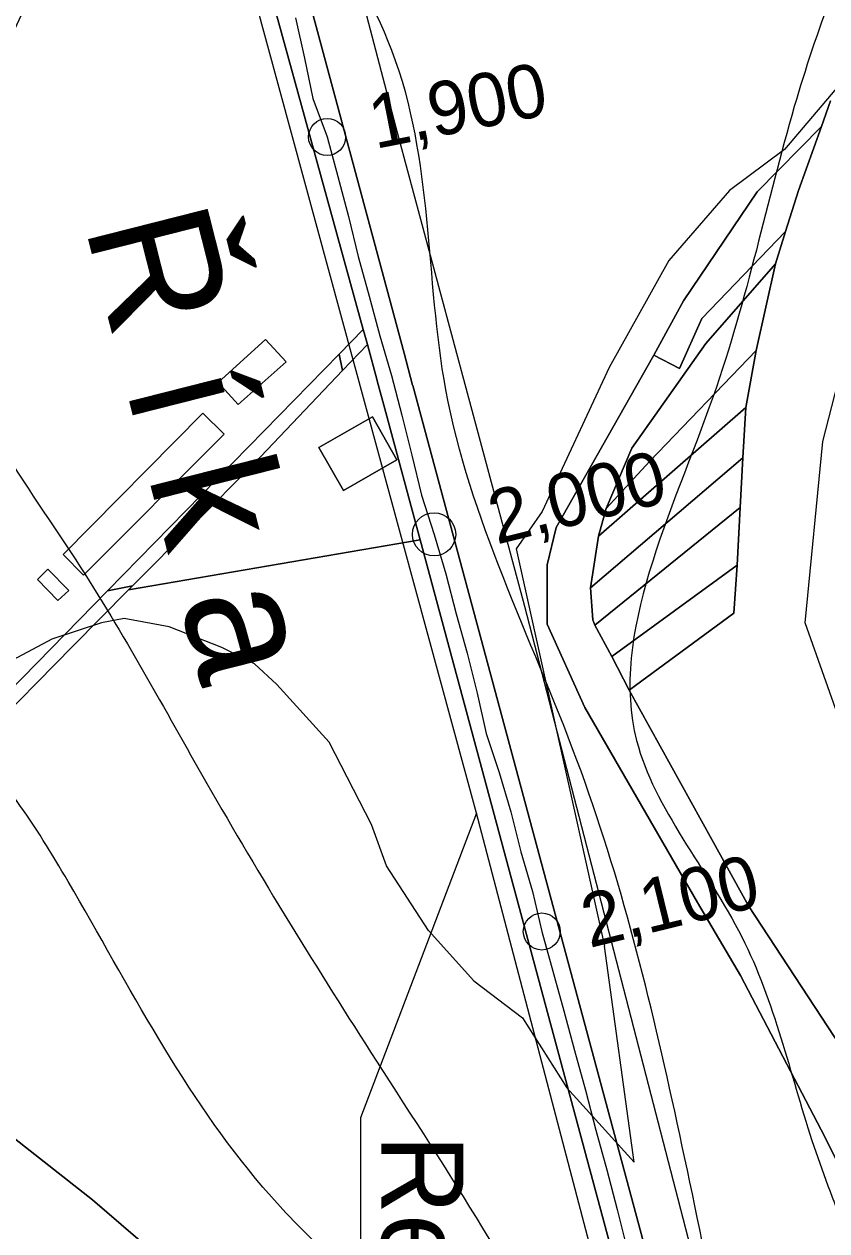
# Model space of a CAD drawing. Extents: x -510989 to -501240, y -1184665 to -1176089.
# Drawn here: x -504809.1 to -504614, y -1181469.7 to -1181176.6 of the extents above; entities that cross this region are included whole.
import ezdxf

# ---------------------------------------------------------------- set-up
doc = ezdxf.new("R2010")
doc.units = 0
for name, color, linetype in [('NAVRH_revitalizace_toku', 7, 'Continuous'), ('orna_puda', 7, 'Continuous'), ('ostatni_plocha_x_draha', 7, 'Continuous'), ('ostatni_plocha_x_jina_plocha', 7, 'Continuous'), ('ostatni_plocha_x_ostatni_komunikace', 7, 'Continuous'), ('ostatni_plocha_x_sportoviste_a_rekr_plocha', 7, 'Continuous'), ('STAV_zaplavove_uzemi', 7, 'Continuous'), ('trasovani_toku', 7, 'Continuous'), ('vodni_plocha_x_vodni_tok_v_koryt_prir_n_upr', 7, 'Continuous'), ('vrstevnice_01', 7, 'Continuous'), ('vrstevnice_02', 7, 'Continuous'), ('zastavena_plocha_a_nadvori', 7, 'Continuous')]:
    doc.layers.add(name, color=color, linetype=linetype)

msp = doc.modelspace()

# ---------------------------------------------------------------- linework, layer by layer
at = {"layer": 'NAVRH_revitalizace_toku'}
for points in [[(-504182.04, -1180792.04), (-504204.87, -1180813.12), (-504441.3, -1180893.49), (-504535.64, -1180920.73), (-504547.6, -1180927.38), (-504622.01, -1180977.87), (-504664.53, -1181014.41), (-504691.11, -1181051.62), (-504730.92, -1181097.66), (-504738.16, -1181127.41), (-504718.87, -1181201.36), (-504687.51, -1181317.93), (-504646.6, -1181475.99), (-504595.04, -1181660.81)], [(-504619.38, -1181665.94), (-504652.45, -1181546.29), (-504699.14, -1181368.28), (-504767.85, -1181115.82)], [(-504699.14, -1181368.28), (-504727.32, -1181442.23), (-504727.15, -1181617.42)]]:
    msp.add_lwpolyline(points, dxfattribs=at)
at = {"layer": 'orna_puda'}
for points in [[(-504609.62, -1181654.37), (-504714.66, -1181264.33), (-504714.68, -1181264.25), (-504716.76, -1181256.52), (-504751.58, -1181127.22), (-504752.67, -1181115.82), (-504749.63, -1181100.59), (-504733.91, -1181066.63), (-504677.14, -1181000.88), (-504645.58, -1180971.03), (-504557.05, -1180910.28)], [(-504613.13, -1181195.22), (-504615.31, -1181201.45), (-504630.96, -1181217.3), (-504648.9, -1181243.78), (-504656.11, -1181257), (-504679.79, -1181298.82), (-504681.95, -1181307.89), (-504681.99, -1181322.34), (-504672.85, -1181342.61), (-504645.47, -1181389.98), (-504634.98, -1181407.71), (-504614.42, -1181447.03), (-504604.62, -1181466.71)], [(-504604.62, -1181466.71), (-504614.42, -1181447.03), (-504634.98, -1181407.71), (-504645.47, -1181389.98), (-504672.85, -1181342.61), (-504681.99, -1181322.34), (-504681.95, -1181307.89), (-504679.79, -1181298.82), (-504656.11, -1181257), (-504649.83, -1181260.24), (-504644.42, -1181248.07), (-504624.08, -1181226.97), (-504626.48, -1181234.83), (-504643.41, -1181254.13), (-504661.43, -1181279.57), (-504667.62, -1181294.22), (-504669.52, -1181300.97), (-504671.47, -1181313.52), (-504670.91, -1181321.27), (-504670.38, -1181322.61), (-504666.3, -1181330.17), (-504662.07, -1181338.33), (-504641.94, -1181374.66), (-504633.05, -1181390.72), (-504607.29, -1181430.02)], [(-504833.48, -1181474.49), (-504875.32, -1181461.1), (-504900.47, -1181432.41), (-504866.87, -1181398.49), (-504862.77, -1181403.54), (-504857.98, -1181408.64), (-504847.86, -1181418.69), (-504792.48, -1181462.19), (-504731.58, -1181514.6)]]:
    msp.add_lwpolyline(points, dxfattribs=at)
for points in [[(-504615.31, -1181201.45), (-504620.93, -1181217), (-504624.08, -1181226.97), (-504644.42, -1181248.07), (-504649.83, -1181260.24), (-504656.11, -1181257), (-504648.9, -1181243.78), (-504630.96, -1181217.3)], [(-504626.48, -1181234.83), (-504631.24, -1181255.86), (-504657.03, -1181282.77), (-504667.62, -1181294.22), (-504661.43, -1181279.57), (-504643.41, -1181254.13)], [(-504725.66, -1181254.39), (-504723.31, -1181263.13), (-504723.29, -1181263.22), (-504721.2, -1181270.94), (-504712.86, -1181301.83), (-504783.7, -1181313.99), (-504782.76, -1181313.04), (-504753.12, -1181283.2), (-504731.68, -1181260.7)], [(-504631.24, -1181255.86), (-504633.68, -1181269.68), (-504669.52, -1181300.97), (-504667.62, -1181294.22), (-504657.03, -1181282.77)], [(-504737.48, -1181279.46), (-504731.51, -1181289.87), (-504718.49, -1181282.4), (-504724.47, -1181271.99)], [(-504633.68, -1181269.68), (-504634.41, -1181281.92), (-504671.47, -1181313.52), (-504669.52, -1181300.97)], [(-504634.41, -1181281.92), (-504635.12, -1181294), (-504670.38, -1181322.61), (-504670.91, -1181321.27), (-504671.47, -1181313.52)], [(-504635.12, -1181294), (-504635.8, -1181308), (-504666.3, -1181330.17), (-504670.38, -1181322.61)], [(-504783.7, -1181313.99), (-504712.86, -1181301.83), (-504662.52, -1181488.46), (-504731.58, -1181514.6), (-504792.48, -1181462.19), (-504847.86, -1181418.69), (-504857.98, -1181408.64), (-504862.77, -1181403.54), (-504866.87, -1181398.49), (-504866.31, -1181397.92), (-504864.53, -1181396.11), (-504862.24, -1181393.77), (-504797.28, -1181327.66)], [(-504635.8, -1181308), (-504636.64, -1181319.66), (-504662.07, -1181338.33), (-504666.3, -1181330.17)]]:
    msp.add_lwpolyline(points, close=True, dxfattribs=at)
at = {"layer": 'ostatni_plocha_x_draha'}
msp.add_lwpolyline([(-504607.29, -1181430.02), (-504633.05, -1181390.72), (-504641.94, -1181374.66), (-504662.07, -1181338.33), (-504636.64, -1181319.66), (-504635.8, -1181308), (-504635.12, -1181294), (-504634.41, -1181281.92), (-504633.68, -1181269.68), (-504631.24, -1181255.86), (-504626.48, -1181234.83), (-504624.08, -1181226.97), (-504620.93, -1181217), (-504615.31, -1181201.45), (-504613.13, -1181195.22)], dxfattribs=at)
at = {"layer": 'ostatni_plocha_x_jina_plocha'}
msp.add_lwpolyline([(-504737.48, -1181279.46), (-504724.47, -1181271.99), (-504718.49, -1181282.4), (-504731.51, -1181289.87)], close=True, dxfattribs=at)
at = {"layer": 'ostatni_plocha_x_ostatni_komunikace'}
for points in [[(-504726.28, -1181252.1), (-504725.66, -1181254.39), (-504731.68, -1181260.7), (-504732.57, -1181256.77), (-504726.66, -1181250.72)], [(-504731.68, -1181260.7), (-504753.12, -1181283.2), (-504782.76, -1181313.04), (-504788.79, -1181314.23), (-504750.73, -1181275.38), (-504732.57, -1181256.77)], [(-504783.7, -1181313.99), (-504797.28, -1181327.66), (-504862.24, -1181393.77), (-504864.28, -1181391.38), (-504788.79, -1181314.23), (-504782.76, -1181313.04)]]:
    msp.add_lwpolyline(points, close=True, dxfattribs=at)
at = {"layer": 'ostatni_plocha_x_sportoviste_a_rekr_plocha'}
msp.add_lwpolyline([(-504760.66, -1181127.46), (-504726.66, -1181250.72), (-504732.57, -1181256.77), (-504750.73, -1181275.38), (-504788.79, -1181314.23), (-504864.28, -1181391.38), (-504904.47, -1181432.44), (-504902.62, -1181434.58), (-504905.19, -1181437.02), (-504905.4, -1181440.61), (-504905.46, -1181441.72), (-504910.13, -1181446.83), (-504925.8, -1181463.98), (-504930.57, -1181459.1), (-505050.59, -1181336.35)], dxfattribs=at)
for points in [[(-504745.4, -1181258.63), (-504750.41, -1181253.22), (-504761.95, -1181263.61), (-504757.11, -1181269.01)], [(-504760.5, -1181276.22), (-504765.62, -1181271.1), (-504799.58, -1181305.39), (-504794.66, -1181310.46)], [(-504805.8, -1181311.48), (-504800.88, -1181316.62), (-504798.2, -1181314.14), (-504803.33, -1181308.99)]]:
    msp.add_lwpolyline(points, close=True, dxfattribs=at)
at = {"layer": 'STAV_zaplavove_uzemi'}
for points in [[(-504594.17, -1181642.09), (-504629.77, -1181535.28), (-504650.39, -1181443.46), (-504674.75, -1181355.39), (-504706.6, -1181265.44), (-504719.72, -1181182.99), (-504747.83, -1181113.66), (-504727.29, -1181064.42), (-504683.65, -1181020.77), (-504624.52, -1180967.28), (-504575.24, -1180927.85), (-504544.27, -1180915.18), (-504445.72, -1180881.39), (-504404.89, -1180867.31), (-504292.26, -1180829.3), (-504179.63, -1180791.29), (-504099.38, -1180734.98), (-504020.54, -1180698.37), (-503957.18, -1180675.84), (-503893.83, -1180664.58), (-503865.67, -1180678.66), (-503817.8, -1180689.92), (-503788.24, -1180689.92), (-503764.3, -1180695.55), (-503736.15, -1180687.11), (-503717.85, -1180698.37), (-503716.44, -1180708.23)], [(-502250.32, -1184002.61), (-502355.07, -1183875.41), (-502442.37, -1183790.61), (-502477.29, -1183700.82), (-502532.16, -1183578.61), (-502567.08, -1183448.91), (-502626.05, -1183402.34), (-502705.41, -1183380.59), (-502814.2, -1183349.87), (-502882.03, -1183297.39), (-502931.95, -1183237.24), (-503042.02, -1183107.97), (-503139.64, -1183018.94), (-503222.14, -1182957.59), (-503308.56, -1182839.96), (-503316.24, -1182784.92), (-503330.32, -1182756.77), (-503348.24, -1182719.65), (-503334.16, -1182651.82), (-503323.92, -1182595.5), (-503313.68, -1182526.39), (-503294.1, -1182480.5), (-503251.86, -1182396.03), (-503229.34, -1182314.37), (-503216.1, -1182227.15), (-503242.43, -1182174.5), (-503271.86, -1182129.59), (-503287.34, -1182081.58), (-503343.88, -1182028.1), (-503361.79, -1182008.91), (-503396.35, -1181952.59), (-503442.43, -1181933.39), (-503497.46, -1181888.6), (-503525.62, -1181860.44), (-503528.18, -1181837.4), (-503548.66, -1181767.01), (-503558.9, -1181729.89), (-503576.82, -1181682.53), (-503578.1, -1181621.1), (-503567.86, -1181572.46), (-503552.5, -1181536.63), (-503538.04, -1181458.36), (-503518.33, -1181411.9), (-503509.88, -1181341.51), (-503497.21, -1181207.63), (-503499.77, -1181097.56), (-503498.02, -1181031.35), (-503510.82, -1180970.85), (-503549.22, -1180952.23), (-503571.32, -1180940.6), (-503605.07, -1180937.11), (-503651.61, -1180939.44), (-503671.39, -1180917.33), (-503679.53, -1180892.89), (-503713.27, -1180871.95), (-503727.24, -1180859.15), (-503734.22, -1180833.55), (-503728.4, -1180799.81), (-503741.2, -1180770.72), (-503722.82, -1180725.17), (-503721.54, -1180703.41), (-503731.78, -1180697.01), (-503767.61, -1180699.57), (-503790.65, -1180697.01), (-503817.53, -1180697.01), (-503861.04, -1180686.77), (-503889.2, -1180675.25), (-503900.72, -1180668.85), (-503953.2, -1180679.09), (-503997.99, -1180697.01), (-504063.27, -1180722.61), (-504109.34, -1180749.49), (-504142.62, -1180776.36), (-504177.18, -1180796.84), (-504211.73, -1180817.32), (-504414.98, -1180961.5), (-504472.7, -1180998.11), (-504544.51, -1181068.5), (-504600.82, -1181143.12), (-504621.94, -1181196.62), (-504641.65, -1181267.01), (-504660.25, -1181350.62), (-504634.7, -1181398.32), (-504617.66, -1181447.72), (-504600.62, -1181492.01), (-504587, -1181548.23), (-504592.11, -1181628.29), (-504569.96, -1181682.81), (-504568.26, -1181664.07), (-504554.63, -1181621.48), (-504547.82, -1181597.63)], [(-504826.46, -1182247.73), (-504827.62, -1182204.68), (-504817.15, -1182165.12), (-504791.55, -1182113.93), (-504727.56, -1182034.81), (-504708.94, -1182017.35), (-504669.38, -1181991.76), (-504649.6, -1181961.5), (-504628.66, -1181917.29), (-504601.9, -1181867.26), (-504597.24, -1181809.08), (-504585.16, -1181766.79), (-504596.8, -1181741.4), (-504604.2, -1181726.59), (-504633.82, -1181658.9), (-504646.51, -1181600.72), (-504660.26, -1181556.29), (-504751.04, -1181459.08), (-504798.4, -1181384.84), (-504826.55, -1181347.73), (-504862.39, -1181315.73), (-504866.23, -1181265.81), (-504862.39, -1181205.66), (-504853.43, -1181164.7), (-504793.92, -1181116.47), (-504755.84, -1181064.64), (-504725.17, -1181018.1), (-504649.01, -1180947.23), (-504594, -1180900.69), (-504545.35, -1180879.53), (-504377.38, -1180832.83), (-504317.01, -1180808.36), (-504368.93, -1180802.59), (-504426.63, -1180826.63), (-504542.02, -1180859.32)], [(-504777.81, -1181111.78), (-504815.29, -1181186.74), (-504828.41, -1181242.96), (-504796.55, -1181306.67), (-504764.69, -1181361.01), (-504723.47, -1181428.47), (-504674.75, -1181510.92), (-504648.51, -1181582.13), (-504622.28, -1181672.07)]]:
    msp.add_spline(points, degree=3, dxfattribs=at)
at = {"layer": 'trasovani_toku'}
for p, q in [((-504743.16, -1181175.06), (-504740.99, -1181184.83)), ((-504740.99, -1181184.83), (-504738.96, -1181194.62)), ((-504738.96, -1181194.62), (-504735.46, -1181203.99)), ((-504735.46, -1181203.99), (-504732.82, -1181213.63)), ((-504732.82, -1181213.63), (-504730.24, -1181223.29)), ((-504730.24, -1181223.29), (-504727.94, -1181233.03)), ((-504727.94, -1181233.03), (-504725.21, -1181242.64)), ((-504725.21, -1181242.64), (-504722.64, -1181252.31)), ((-504722.64, -1181252.31), (-504719.82, -1181261.9)), ((-504719.82, -1181261.9), (-504717.32, -1181271.59)), ((-504717.32, -1181271.59), (-504714.88, -1181281.28)), ((-504714.88, -1181281.28), (-504712.54, -1181291)), ((-504712.54, -1181291), (-504709.47, -1181300.52)), ((-504709.47, -1181300.52), (-504706.61, -1181310.1)), ((-504706.61, -1181310.1), (-504704.11, -1181319.79)), ((-504704.11, -1181319.79), (-504701.42, -1181329.42)), ((-504701.42, -1181329.42), (-504698.97, -1181339.12)), ((-504698.97, -1181339.12), (-504696.79, -1181348.87)), ((-504696.79, -1181348.87), (-504693.66, -1181358.37)), ((-504693.66, -1181358.37), (-504690.81, -1181367.96)), ((-504690.81, -1181367.96), (-504688.41, -1181377.66)), ((-504688.41, -1181377.66), (-504685.53, -1181387.24)), ((-504685.53, -1181387.24), (-504683.29, -1181396.99)), ((-504683.29, -1181396.99), (-504680.61, -1181406.62)), ((-504680.61, -1181406.62), (-504677.97, -1181416.26)), ((-504677.97, -1181416.26), (-504675.38, -1181425.92)), ((-504675.38, -1181425.92), (-504672.71, -1181435.56)), ((-504672.71, -1181435.56), (-504670.16, -1181445.23)), ((-504670.16, -1181445.23), (-504667.51, -1181454.87)), ((-504667.51, -1181454.87), (-504664.94, -1181464.54)), ((-504664.94, -1181464.54), (-504662.53, -1181474.24))]:
    msp.add_line(p, q, dxfattribs=at)
for centre, radius in [((-504735.46, -1181203.99), 4.5), ((-504709.47, -1181300.52), 5.25), ((-504683.29, -1181396.99), 4.5)]:
    msp.add_circle(centre, radius, dxfattribs=at)
at = {"layer": 'vodni_plocha_x_vodni_tok_v_koryt_prir_n_upr'}
for points in [[(-504608.12, -1181659.96), (-504614.86, -1181665.13), (-504632.61, -1181599.34), (-504645.61, -1181551.13), (-504655.26, -1181515.38), (-504662.52, -1181488.46), (-504712.86, -1181301.83), (-504721.2, -1181270.94), (-504723.29, -1181263.22), (-504723.31, -1181263.13), (-504725.66, -1181254.39), (-504726.28, -1181252.1), (-504726.66, -1181250.72), (-504760.66, -1181127.46), (-504762.01, -1181115.76), (-504759.3, -1181101.6), (-504742.72, -1181064.52), (-504687.23, -1180996.05), (-504653.08, -1180963.75), (-504566.19, -1180904.56)], [(-504557.05, -1180910.28), (-504645.58, -1180971.03), (-504677.14, -1181000.88), (-504733.91, -1181066.63), (-504749.63, -1181100.59), (-504752.67, -1181115.82), (-504751.58, -1181127.22), (-504716.76, -1181256.52), (-504714.68, -1181264.25), (-504714.66, -1181264.33), (-504609.62, -1181654.37)]]:
    msp.add_lwpolyline(points, dxfattribs=at)
at = {"layer": 'vrstevnice_01'}
for points in [[(-504610.69, -1181191), (-504624.31, -1181207), (-504637.69, -1181217), (-504652.41, -1181234), (-504666.91, -1181260), (-504683.19, -1181295), (-504689.5, -1181304), (-504668.06, -1181400.59)], [(-504710.84, -1181396.73), (-504721, -1181381), (-504724.69, -1181371), (-504735, -1181351), (-504747.69, -1181337), (-504753.09, -1181332), (-504761, -1181328), (-504773.81, -1181323), (-504784.81, -1181321), (-504790.31, -1181322), (-504802.31, -1181326), (-504832.5, -1181342)], [(-504710.84, -1181396.73), (-504699.81, -1181409), (-504688, -1181418), (-504677.19, -1181435), (-504660.81, -1181453), (-504668.06, -1181400.59)]]:
    msp.add_lwpolyline(points, dxfattribs=at)
at = {"layer": 'vrstevnice_02'}
msp.add_lwpolyline([(-504588.91, -1181407.73), (-504619.31, -1181322), (-504615, -1181278), (-504604.69, -1181238)], dxfattribs=at)
at = {"layer": 'zastavena_plocha_a_nadvori'}
for points in [[(-504745.4, -1181258.63), (-504757.11, -1181269.01), (-504761.95, -1181263.61), (-504750.41, -1181253.22)], [(-504760.5, -1181276.22), (-504794.66, -1181310.46), (-504799.58, -1181305.39), (-504765.62, -1181271.1)], [(-504805.8, -1181311.48), (-504803.33, -1181308.99), (-504798.2, -1181314.14), (-504800.88, -1181316.62)]]:
    msp.add_lwpolyline(points, close=True, dxfattribs=at)

# ---------------------------------------------------------------- texts
at = {"layer": 'NAVRH_revitalizace_toku'}
msp.add_text('Revitalizace toku', height=20, rotation=270, dxfattribs=at).set_placement((-504722.32, -1181446.36))
at = {"layer": 'trasovani_toku'}
for s, height, rotation, p in [('1,900', 13, 11.2618, (-504723.81, -1181206.94)), ('Ř í k a', 30, 284.2265, (-504794.36, -1181225.62)), ('2,000', 13, 14.0419, (-504694.29, -1181303.03)), ('2,100', 13, 13.7964, (-504671.73, -1181401.03))]:
    msp.add_text(s, height=height, rotation=rotation, dxfattribs=at).set_placement(p)

doc.saveas('drawing.dxf')
